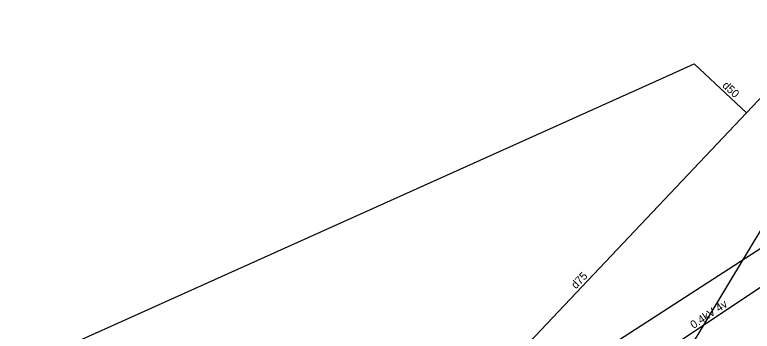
# Model space of a CAD drawing. Extents: x 469981 to 472086, y 246785 to 247785.
# Drawn here: x 470167.11 to 470213.16, y 246963.3 to 246983.07 of the extents above; entities that cross this region are included whole.
import ezdxf

# ---------------------------------------------------------------- set-up
doc = ezdxf.new("R2010")
doc.units = 0
for name, color, linetype in [('DREN_VADP_####_####_#', 7, 'Continuous'), ('DREN_VADP_####_TKST_#', 7, 'Continuous'), ('DREN_VADP_KLKT_####_#', 7, 'Continuous'), ('DREN_VADP_KLKT_TKST_#', 7, 'Continuous'), ('ELEK_VADV_ZSPR_####_#', 7, 'Continuous'), ('ELEK_VADV_ZSPR_TKST_#', 7, 'Continuous'), ('RAMI_UZMR_####_####_#', 7, 'Continuous'), ('RELJ_NOGA_####_####_#', 7, 'Continuous'), ('RELJ_NOGL_####_####_#', 7, 'Continuous')]:
    doc.layers.add(name, color=color, linetype=linetype)

msp = doc.modelspace()

# ---------------------------------------------------------------- linework, layer by layer
at = {"layer": 'DREN_VADP_####_####_#'}
for points in [[(470080.047, 246875.138), (470127.803, 246906.822), (470151.116, 246922.29), (470207.903, 246959.965), (470213.971, 246970.06), (470227.513, 246992.59), (470228.7, 246994.565)], [(470067.964, 246916.336), (470207.556, 246979.116), (470209.528, 246980.003), (470212.802, 246976.95)]]:
    msp.add_lwpolyline(points, dxfattribs=at)
at = {"layer": 'DREN_VADP_KLKT_####_#'}
msp.add_lwpolyline([(470072.23, 246882.077), (470123.03, 246913.973), (470146.844, 246928.925), (470197.394, 246960.663), (470212.802, 246976.95), (470229.327, 246994.419)], dxfattribs=at)
at = {"layer": 'ELEK_VADV_ZSPR_####_#'}
msp.add_line((470268.498, 247002.594), (470200.795, 246957.454), dxfattribs=at)
at = {"layer": 'RAMI_UZMR_####_####_#'}
msp.add_lwpolyline([(470081.833, 246858.073), (470071.225, 246873.795), (470075.411, 246878.04), (470140.155, 246920.953), (470236.136, 246982.998), (470257.83, 246999.315), (470274.171, 247013.774), (470358.465, 247102.148), (470367.97, 247107.52), (470388.133, 247118.916), (470465.996, 247150.017), (470560.64, 247175.144), (470793.366, 247232.231)], dxfattribs=at)
at = {"layer": 'RELJ_NOGA_####_####_#'}
for points in [[(470120.845, 246890.769), (470123.591, 246892.466), (470150.351, 246909.177), (470171.26, 246922.106), (470191.149, 246935.734), (470210.204, 246948.514), (470224.202, 246958.074), (470243.113, 246970.411), (470266.522, 246987.913), (470280.536, 247001.251), (470299.823, 247020.383), (470317.592, 247038.544), (470334.877, 247055.828), (470351.425, 247073.192), (470366.151, 247085.967)], [(470191.297, 246946.326), (470199.076, 246951.08), (470206.775, 246955.957), (470212.93, 246960.227), (470219.069, 246964.52), (470221.779, 246966.326), (470230.031, 246971.567), (470235.51, 246975.093), (470238.207, 246976.92), (470240.857, 246978.815), (470250.613, 246986.265), (470260.213, 246993.913), (470261.356, 246994.83)]]:
    msp.add_spline(points, degree=3, dxfattribs=at)
at = {"layer": 'RELJ_NOGL_####_####_#'}
for points in [[(470122.047, 246889.925), (470124.645, 246891.606), (470151.263, 246908.028), (470171.623, 246921.498), (470191.873, 246934.822), (470224.882, 246957.282), (470243.432, 246969.856), (470267.182, 246986.981), (470282.015, 246999.84), (470300.677, 247018.663), (470318.825, 247036.845), (470336.227, 247054.122), (470352.943, 247071.373), (470367.141, 247084.447)], [(470260.657, 246995.044), (470259.659, 246994.389), (470254.708, 246990.877), (470249.918, 246987.138), (470245.145, 246983.372), (470240.25, 246979.781), (470234.784, 246976.183), (470229.231, 246972.715), (470223.673, 246969.252), (470218.195, 246965.673), (470215.126, 246963.517), (470212.091, 246961.309), (470205.961, 246956.98), (470198.279, 246952.125), (470190.54, 246947.358)]]:
    msp.add_spline(points, degree=3, dxfattribs=at)

# ---------------------------------------------------------------- texts
at = {"layer": 'DREN_VADP_####_TKST_#'}
msp.add_text('d50', height=0.5, rotation=317.0005, dxfattribs=at).set_placement((470211.256, 246978.597))
at = {"layer": 'DREN_VADP_KLKT_TKST_#'}
msp.add_text('d75', height=0.5, rotation=46.5884, dxfattribs=at).set_placement((470202.156, 246965.914))
at = {"layer": 'ELEK_VADV_ZSPR_TKST_#'}
msp.add_text('0.4kV 4v', height=0.5, rotation=33.6929, dxfattribs=at).set_placement((470209.5, 246963.438))

doc.saveas('drawing.dxf')
